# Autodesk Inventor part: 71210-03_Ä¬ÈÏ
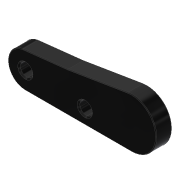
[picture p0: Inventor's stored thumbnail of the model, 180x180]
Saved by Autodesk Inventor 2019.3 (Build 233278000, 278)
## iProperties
Created: 2010-06
Part Number: 71210-03_Ä¬ÈÏ
Material: Ogólny
Document SubType Name: Modeling
Designer: CADENGINEERING4
Density: 1 g/cm^3
Appearance: Gładki — czarny
Author: CADENGINEERING4
Revision Number: ÈÎºÎ
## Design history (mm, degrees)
feature "NONE"
node "Bryła1"
